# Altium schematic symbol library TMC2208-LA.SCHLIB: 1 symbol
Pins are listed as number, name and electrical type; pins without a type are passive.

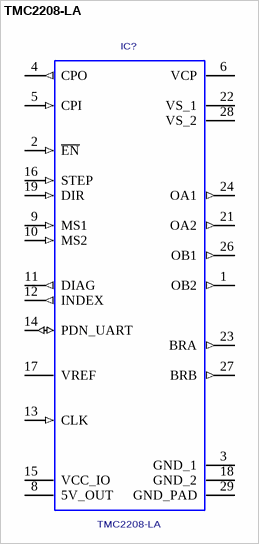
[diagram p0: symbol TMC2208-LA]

## TMC2208-LA
designator IC?
Ultra-silent Step/Dir Driver for two-Phase bipolar Stepper Motors, with STEP/DIR, UART, QFN28(5x5); Manufacturer: TRINAMIC; Geometry.Height: 0.9mm; PCB DECAL: TMC_QFN28_0.5_5.0X5.0
footprint TMC_QFN28_0.5_5.0X5.0
pins: 1 OB2 (out), 2 ~{EN} (in), 3 GND_1 (power), 4 CPO (out), 5 CPI (in), 6 VCP (power), 8 5V_OUT (power), 9 MS1 (in), 10 MS2 (in), 11 DIAG (out), 12 INDEX (out), 13 CLK (in), 14 PDN_UART (io), 15 VCC_IO (power), 16 STEP (in), 17 VREF (power), 18 GND_2 (power), 19 DIR (in), 21 OA2 (out), 22 VS_1 (power), 23 BRA (out), 24 OA1 (out), 26 OB1 (out), 27 BRB (out), 28 VS_2 (power), 29 GND_PAD (power)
